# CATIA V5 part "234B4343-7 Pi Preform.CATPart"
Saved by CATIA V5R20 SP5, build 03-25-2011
Part number: 234B4343-7 Pi Preform
Bounding box of the stored display mesh (mm): x 31591.25 to 31877.773, y -11281.794 to -11167.477, z 5343.684 to 5407.082
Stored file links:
  C:\Users\rem1927\Desktop\Current Explicit Composite Demo\234B4343-7 Pi Preform.CATPart
  C:\Users\rem1927\Desktop\Current Explicit Composite Demo\234B5678-1 Composite Product.CATProduct
  C:\Users\rem1927\Desktop\Current Explicit Composite Demo\234B5678_2_Rev_.CATPart
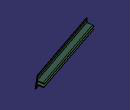
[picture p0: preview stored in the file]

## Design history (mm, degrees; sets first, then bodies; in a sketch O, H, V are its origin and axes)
Parameters
  Material = "Composite Pultrusion"
WSupportSet1: ActiveGrid {wsupport Support Plane1, RefPoint Intersect1, GridIn {cartgrid StepH1 25.4, StepH2 100, StepV1 25.4, StepV2 100, Direction Plane2}}
Set1
  Intersect1: ToIntersect1 Plane1, ToIntersect2 DatumCurve1
  Point1: type OnPlane, OnSupport {wsupport Support Plane1, RefPoint Intersect1, GridIn {cartgrid StepH1 25.4, StepH2 100, StepV1 25.4, StepV2 100, Direction Plane2}}, Support Plane1, RefPoint Intersect1, H 0, V 25.4, Direction Plane2
  Point2: type OnPlane, OnSupport {wsupport Support Plane1, RefPoint Intersect1, GridIn {cartgrid StepH1 25.4, StepH2 100, StepV1 25.4, StepV2 100, Direction Plane2}}, Support Plane1, RefPoint Intersect1, H 0, V -25.4, Direction Plane2
  Point3: type OnPlane, OnSupport {wsupport Support Plane1, RefPoint Intersect1, GridIn {cartgrid StepH1 25.4, StepH2 100, StepV1 25.4, StepV2 100, Direction Plane2}}, Support Plane1, RefPoint Intersect1, H 1.27, V 25.4, Direction Plane2
  Point4: type OnPlane, OnSupport {wsupport Support Plane1, RefPoint Intersect1, GridIn {cartgrid StepH1 25.4, StepH2 100, StepV1 25.4, StepV2 100, Direction Plane2}}, Support Plane1, RefPoint Intersect1, H 1.27, V -25.4, Direction Plane2
  Point5: type OnPlane, OnSupport {wsupport Support Plane1, RefPoint Intersect1, GridIn {cartgrid StepH1 25.4, StepH2 100, StepV1 25.4, StepV2 100, Direction Plane2}}, Support Plane1, RefPoint Intersect1, H 2.54, V 20.32, Direction Plane2
  Point6: type OnPlane, OnSupport {wsupport Support Plane1, RefPoint Intersect1, GridIn {cartgrid StepH1 25.4, StepH2 100, StepV1 25.4, StepV2 100, Direction Plane2}}, Support Plane1, RefPoint Intersect1, H 2.54, V -20.32, Direction Plane2
  Point7: type OnPlane, OnSupport {wsupport Support Plane1, RefPoint Intersect1, GridIn {cartgrid StepH1 25.4, StepH2 100, StepV1 25.4, StepV2 100, Direction Plane2}}, Support Plane1, RefPoint Intersect1, H 2.54, V 7.62, Direction Plane2
  Point8: type OnPlane, OnSupport {wsupport Support Plane1, RefPoint Intersect1, GridIn {cartgrid StepH1 25.4, StepH2 100, StepV1 25.4, StepV2 100, Direction Plane2}}, Support Plane1, RefPoint Intersect1, H 2.54, V -7.62, Direction Plane2
  Point9: type OnPlane, OnSupport {wsupport Support Plane1, RefPoint Intersect1, GridIn {cartgrid StepH1 25.4, StepH2 100, StepV1 25.4, StepV2 100, Direction Plane2}}, Support Plane1, RefPoint Intersect1, H 2.54, V -5.08, Direction Plane2
  Point10: type OnPlane, OnSupport {wsupport Support Plane1, RefPoint Intersect1, GridIn {cartgrid StepH1 25.4, StepH2 100, StepV1 25.4, StepV2 100, Direction Plane2}}, Support Plane1, RefPoint Intersect1, H 25.4, V 7.62, Direction Plane2
  Point11: type OnPlane, OnSupport {wsupport Support Plane1, RefPoint Intersect1, GridIn {cartgrid StepH1 25.4, StepH2 100, StepV1 25.4, StepV2 100, Direction Plane2}}, Support Plane1, RefPoint Intersect1, H 25.4, V -7.62, Direction Plane2
  Point12: type OnPlane, OnSupport {wsupport Support Plane1, RefPoint Intersect1, GridIn {cartgrid StepH1 25.4, StepH2 100, StepV1 25.4, StepV2 100, Direction Plane2}}, Support Plane1, RefPoint Intersect1, H 25.4, V -5.08, Direction Plane2
  Point13: type OnPlane, OnSupport {wsupport Support Plane1, RefPoint Intersect1, GridIn {cartgrid StepH1 25.4, StepH2 100, StepV1 25.4, StepV2 100, Direction Plane2}}, Support Plane1, RefPoint Intersect1, H 0, V 25.4, Direction Plane2
  Point14: type OnPlane, OnSupport {wsupport Support Plane1, RefPoint Intersect1, GridIn {cartgrid StepH1 25.4, StepH2 100, StepV1 25.4, StepV2 100, Direction Plane2}}, Support Plane1, RefPoint Intersect1, H 25.4, V 5.08, Direction Plane2
  Point15: type OnPlane, OnSupport {wsupport Support Plane1, RefPoint Intersect1, GridIn {cartgrid StepH1 25.4, StepH2 100, StepV1 25.4, StepV2 100, Direction Plane2}}, Support Plane1, RefPoint Intersect1, H 2.54, V 5.08, Direction Plane2
  Line1: type PtPt, OnSupport {wsupport Support Plane1, RefPoint Intersect1, GridIn {cartgrid StepH1 25.4, StepH2 100, StepV1 25.4, StepV2 100, Direction Plane2}}, FirstPoint Point13, SecondPoint Point2, Support Plane1
  Line2: type PtPt, OnSupport {wsupport Support Plane1, RefPoint Intersect1, GridIn {cartgrid StepH1 25.4, StepH2 100, StepV1 25.4, StepV2 100, Direction Plane2}}, FirstPoint Point2, SecondPoint Point4, Support Plane1
  Line3: type PtPt, OnSupport {wsupport Support Plane1, RefPoint Intersect1, GridIn {cartgrid StepH1 25.4, StepH2 100, StepV1 25.4, StepV2 100, Direction Plane2}}, FirstPoint Point6, SecondPoint Point4, Support Plane1
  Line4: type PtPt, OnSupport {wsupport Support Plane1, RefPoint Intersect1, GridIn {cartgrid StepH1 25.4, StepH2 100, StepV1 25.4, StepV2 100, Direction Plane2}}, FirstPoint Point8, SecondPoint Point6, Support Plane1
  Line5: type PtPt, OnSupport {wsupport Support Plane1, RefPoint Intersect1, GridIn {cartgrid StepH1 25.4, StepH2 100, StepV1 25.4, StepV2 100, Direction Plane2}}, FirstPoint Point8, SecondPoint Point11, Support Plane1
  Line6: type PtPt, OnSupport {wsupport Support Plane1, RefPoint Intersect1, GridIn {cartgrid StepH1 25.4, StepH2 100, StepV1 25.4, StepV2 100, Direction Plane2}}, FirstPoint Point12, SecondPoint Point11, Support Plane1
  Line7: type PtPt, OnSupport {wsupport Support Plane1, RefPoint Intersect1, GridIn {cartgrid StepH1 25.4, StepH2 100, StepV1 25.4, StepV2 100, Direction Plane2}}, FirstPoint Point9, SecondPoint Point12, Support Plane1
  Line8: type PtPt, OnSupport {wsupport Support Plane1, RefPoint Intersect1, GridIn {cartgrid StepH1 25.4, StepH2 100, StepV1 25.4, StepV2 100, Direction Plane2}}, FirstPoint Point15, SecondPoint Point9, Support Plane1
  Line9: type PtPt, OnSupport {wsupport Support Plane1, RefPoint Intersect1, GridIn {cartgrid StepH1 25.4, StepH2 100, StepV1 25.4, StepV2 100, Direction Plane2}}, FirstPoint Point14, SecondPoint Point15, Support Plane1
  Line10: type PtPt, OnSupport {wsupport Support Plane1, RefPoint Intersect1, GridIn {cartgrid StepH1 25.4, StepH2 100, StepV1 25.4, StepV2 100, Direction Plane2}}, FirstPoint Point10, SecondPoint Point14, Support Plane1
  Line11: type PtPt, OnSupport {wsupport Support Plane1, RefPoint Intersect1, GridIn {cartgrid StepH1 25.4, StepH2 100, StepV1 25.4, StepV2 100, Direction Plane2}}, FirstPoint Point7, SecondPoint Point10, Support Plane1
  Line12: type PtPt, OnSupport {wsupport Support Plane1, RefPoint Intersect1, GridIn {cartgrid StepH1 25.4, StepH2 100, StepV1 25.4, StepV2 100, Direction Plane2}}, FirstPoint Point7, SecondPoint Point5, Support Plane1
  Line13: type PtPt, OnSupport {wsupport Support Plane1, RefPoint Intersect1, GridIn {cartgrid StepH1 25.4, StepH2 100, StepV1 25.4, StepV2 100, Direction Plane2}}, FirstPoint Point5, SecondPoint Point3, Support Plane1
  Line14: type PtPt, OnSupport {wsupport Support Plane1, RefPoint Intersect1, GridIn {cartgrid StepH1 25.4, StepH2 100, StepV1 25.4, StepV2 100, Direction Plane2}}, FirstPoint Point3, SecondPoint Point1, Support Plane1
  Join1: Elements (Line1; Line2; Line3; Line4; Line5; Line6; Line7; Line8; Line9; Line10; Line11; Line12; Line13; Line14), OnSupport {wsupport Support Plane1, RefPoint Intersect1, GridIn {cartgrid StepH1 25.4, StepH2 100, StepV1 25.4, StepV2 100, Direction Plane2}}
Set2
  Plane1: linked copy from another document
  DatumCurve1: linked copy from another document
  Plane2 "web_surface": linked copy from another document
Body1 "Preform" (main body)
  Pad1: profile Join1, length 241.3, opposite side length 50.8
  Chamfer1: length 5.08, angle 10, on edge [face of Pad1 | face of Pad1]
  Chamfer2: length 5.08, angle 10, on edge [face of Pad1 | face of Pad1]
